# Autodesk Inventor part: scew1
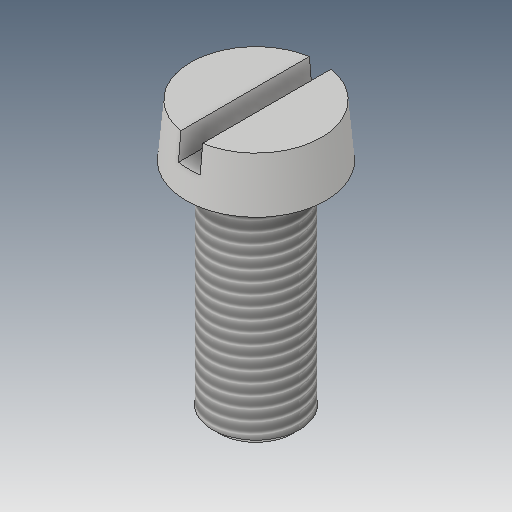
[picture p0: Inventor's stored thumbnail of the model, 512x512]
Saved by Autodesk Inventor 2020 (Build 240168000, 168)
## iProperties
Created: 2016-05
Part Number: scew1
Material: Generic
Document SubType Name: Modeling
Designer: CADCIM
Density: 1 g/cm^3
Appearance: Default
Author: CADCIM
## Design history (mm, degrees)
sketch "Sketch1"
  geometry: C1 r 9.6 at (0, 0); 1 further point
  constraints: 1 centre point, 1 coincident
  dimensions: "d0" = 19.2 diameter of C1
extrude "Extrusion1" new body sketch "Sketch1" distance "d1" = 7.2; taper "d2" = -5 deg
sketch "Sketch3"
  geometry: C1 r 6 at (0, 0); 1 further point
  constraints: 1 centre point, 1 coincident
  dimensions: "d7" = 12 diameter of C1
extrude "Extrusion3" join sketch "Sketch3" distance "d8" = 30; taper "d9" = 0 deg
thread "Thread1" dims "d13" = 10, "d14" = 0
chamfer "Chamfer2" distance "d15" = 0.9; stored, may be unused: second distance "d16" = 2, angle "d17" = 45 deg
sketch "Sketch4"
  geometry: L1 (1.5, -10.35)-(-1.5, -10.35); L2 (-1.5, -10.35)-(-1.5, 10.35); L3 (-1.5, 10.35)-(1.5, 10.35); L4 (1.5, 10.35)-(1.5, -10.35); L5 (0, -10.35)-(0, 10.35); 2 further points
  constraints: 10 end point, 3 midpoint, 2 parallel, 1 coincident, 1 horizontal, 1 perpendicular
  dimensions: "d18" = 3 distance of L1.start L1.end
extrude "Extrusion4" cut sketch "Sketch4" distance "d19" = 3.6; taper "d20" = 0 deg
body "Solid1"
